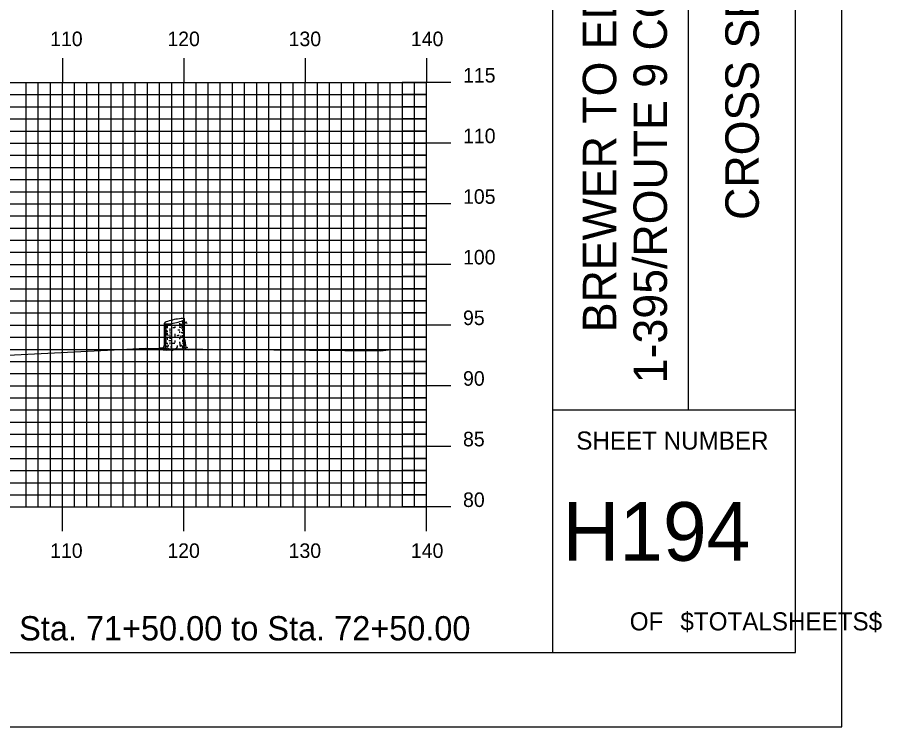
# Model space of a CAD drawing. Extents: x 1760610 to 1760954, y 442591 to 442811.
# Drawn here: x 1760882.5 to 1760953.7, y 442590.5 to 442649 of the extents above; entities that cross this region are included whole.
import ezdxf

# ---------------------------------------------------------------- set-up
doc = ezdxf.new("R2010")
doc.units = 0
for name, color, linetype in [('BORDER', 7, 'Continuous'), ('H_V ANNOTATION', 7, 'Continuous'), ('M_Trees_Conifer_Pay', 7, 'Continuous'), ('MAJOR', 7, 'Continuous'), ('MINOR', 7, 'Continuous'), ('PLOT BOUNDARY', 7, 'Continuous'), ('S_Roadway_Centerline', 7, 'Continuous')]:
    doc.layers.add(name, color=color, linetype=linetype)

msp = doc.modelspace()

# ---------------------------------------------------------------- linework, layer by layer
at = {"layer": 'BORDER'}
for p, q in [((1760926.614, 442596.665), (1760926.614, 442806.665)), ((1760937.796, 442616.671), (1760937.796, 442686.671)), ((1760926.614, 442616.671), (1760946.614, 442616.671))]:
    msp.add_line(p, q, dxfattribs=at)
msp.add_lwpolyline([(1760626.614, 442596.665), (1760946.614, 442596.665), (1760946.614, 442806.665), (1760626.614, 442806.665)], close=True, dxfattribs=at)
at = {"layer": 'M_Trees_Conifer_Pay'}
for p, q in [((1760894.616, 442622.089), (1760894.616, 442623.811)), ((1760894.663, 442623.773), (1760894.663, 442623.302)), ((1760894.722, 442623.762), (1760894.722, 442623.664)), ((1760894.847, 442623.754), (1760894.847, 442623.522)), ((1760895.067, 442623.775), (1760895.067, 442623.607)), ((1760895.863, 442623.817), (1760895.863, 442623.617)), ((1760896.091, 442624.013), (1760896.091, 442623.79)), ((1760896.091, 442623.701), (1760896.091, 442623.654)), ((1760896.209, 442624.074), (1760896.209, 442623.911)), ((1760896.209, 442623.844), (1760896.209, 442623.716)), ((1760896.28, 442622.499), (1760896.28, 442624.146)), ((1760894.663, 442623.238), (1760894.663, 442622.93)), ((1760894.722, 442623.59), (1760894.722, 442623.386)), ((1760894.722, 442623.329), (1760894.722, 442623.129)), ((1760894.722, 442623.082), (1760894.722, 442622.746)), ((1760894.847, 442623.481), (1760894.847, 442623.407)), ((1760894.847, 442623.004), (1760894.847, 442622.865)), ((1760895.067, 442623.37), (1760895.067, 442623.133)), ((1760895.472, 442623.543), (1760895.472, 442623.448)), ((1760895.863, 442623.56), (1760895.863, 442623.471)), ((1760895.863, 442623.123), (1760895.863, 442623.018)), ((1760896.091, 442623.319), (1760896.091, 442623.187)), ((1760896.091, 442623.076), (1760896.091, 442622.966)), ((1760896.148, 442623.518), (1760896.097, 442623.458)), ((1760896.209, 442623.529), (1760896.209, 442623.193)), ((1760896.209, 442623.156), (1760896.209, 442622.993)), ((1760896.209, 442622.946), (1760896.209, 442622.729)), ((1760894.663, 442622.882), (1760894.663, 442622.39)), ((1760894.663, 442622.336), (1760894.663, 442622.089)), ((1760894.722, 442622.693), (1760894.722, 442622.557)), ((1760894.722, 442622.458), (1760894.722, 442622.079)), ((1760894.847, 442622.594), (1760894.847, 442622.452)), ((1760895.067, 442622.888), (1760895.067, 442622.736)), ((1760895.067, 442622.693), (1760895.067, 442622.519)), ((1760895.067, 442622.242), (1760895.067, 442622.089)), ((1760895.472, 442622.93), (1760895.472, 442622.855)), ((1760895.472, 442622.831), (1760895.472, 442622.682)), ((1760895.472, 442622.39), (1760895.472, 442622.237)), ((1760895.863, 442622.651), (1760895.863, 442622.505)), ((1760895.863, 442622.273), (1760895.863, 442622.184)), ((1760896.091, 442622.831), (1760896.091, 442622.689)), ((1760896.091, 442622.462), (1760896.091, 442622.289)), ((1760896.209, 442622.699), (1760896.209, 442622.624)), ((1760896.209, 442622.584), (1760896.209, 442622.411)), ((1760894.847, 442622.19), (1760894.847, 442622.096)), ((1760894.847, 442621.696), (1760895.01, 442621.76)), ((1760895.284, 442621.632), (1760895.158, 442621.696))]:
    msp.add_line(p, q, dxfattribs=at)
for points in [[(1760896.097, 442623.644), (1760896.134, 442623.57), (1760896.181, 442623.627), (1760896.239, 442623.695), (1760896.331, 442623.889), (1760896.396, 442623.936), (1760896.427, 442623.943)], [(1760896.112, 442623.391), (1760896.148, 442623.518), (1760896.212, 442623.634), (1760896.243, 442623.701), (1760896.312, 442623.848)], [(1760896.326, 442623.877), (1760896.402, 442623.885), (1760896.474, 442623.786)], [(1760894.795, 442623.117), (1760894.789, 442623.212), (1760894.833, 442623.189), (1760894.833, 442623.094)], [(1760896.064, 442623.607), (1760896.033, 442623.522), (1760896.029, 442623.455), (1760896.06, 442623.391)], [(1760896.28, 442622.499), (1760896.331, 442622.237), (1760896.348, 442621.964), (1760896.406, 442621.838), (1760896.541, 442621.808), (1760896.311, 442621.77), (1760896.311, 442621.77), (1760896.317, 442621.723), (1760896.564, 442621.628), (1760896.29, 442621.645), (1760895.934, 442621.665), (1760895.613, 442621.655), (1760895.619, 442621.737), (1760895.471, 442621.655), (1760895.284, 442621.632), (1760895.308, 442621.564), (1760895.041, 442621.607), (1760894.82, 442621.581), (1760894.528, 442621.598), (1760894.816, 442621.655), (1760894.847, 442621.696), (1760894.684, 442621.754), (1760894.448, 442621.764), (1760894.207, 442621.764), (1760894.549, 442621.822), (1760894.59, 442621.902), (1760894.616, 442622.089)], [(1760895.934, 442622.718), (1760895.947, 442622.641), (1760895.994, 442622.651), (1760895.982, 442622.818)], [(1760896.206, 442622.357), (1760896.212, 442622.211), (1760896.259, 442622.143), (1760896.27, 442621.943)], [(1760894.664, 442622.042), (1760894.643, 442621.964), (1760894.623, 442621.869)], [(1760894.742, 442622.021), (1760894.748, 442621.906), (1760894.695, 442621.817), (1760894.684, 442621.754)], [(1760894.905, 442622.048), (1760894.905, 442621.916), (1760894.816, 442621.817)], [(1760895.131, 442621.808), (1760895.199, 442621.902), (1760895.226, 442622.042)], [(1760895.619, 442621.737), (1760895.694, 442621.879), (1760895.703, 442621.98)], [(1760895.87, 442622.106), (1760895.881, 442621.98), (1760895.955, 442621.937)], [(1760896.148, 442621.717), (1760896.134, 442621.855), (1760896.06, 442621.984)], [(1760896.107, 442622.211), (1760896.181, 442622.106), (1760896.186, 442621.933), (1760896.311, 442621.77)]]:
    msp.add_lwpolyline(points, dxfattribs=at)
for centre, radius, start, end in [((1760894.643, 442623.811), 0.0264, 169.2194, 180.03145), ((1760894.639, 442623.811), 0.0226, 180.03145, 191.7194), ((1760894.648, 442623.81), 0.0314, 156.51582, 169.2194), ((1760894.639, 442623.811), 0.0226, 191.7194, 203.40735), ((1760894.642, 442623.812), 0.0264, 203.40735, 214.2194), ((1760894.667, 442623.801), 0.0527, 146.7194, 156.51582), ((1760894.647, 442623.815), 0.0314, 214.2194, 226.92298), ((1760894.691, 442623.785), 0.0817, 132.38868, 146.7194), ((1760894.661, 442623.83), 0.0527, 226.92298, 236.7194), ((1760894.677, 442623.855), 0.0817, 236.7194, 251.05013), ((1760894.805, 442623.66), 0.251, 124.2194, 132.38868), ((1760894.732, 442624.014), 0.251, 251.05013, 259.2194), ((1760895.115, 442623.205), 0.802, 108.05939, 124.2194), ((1760894.835, 442624.556), 0.802, 259.2194, 275.37941), ((1760896.472, 442619.043), 5.179, 101.7194, 108.05939), ((1760894.425, 442628.914), 5.179, 275.37941, 281.7194), ((1760895.448, 442627.823), 4.124, 264.6955, 266.73309), ((1760896.472, 442619.043), 5.179, 95.37941, 101.7194), ((1760894.425, 442628.914), 5.179, 281.7194, 288.05939), ((1760895.448, 442627.823), 4.124, 276.23804, 278.1032), ((1760896.062, 442623.401), 0.802, 79.2194, 95.37941), ((1760895.781, 442624.752), 0.802, 288.05939, 304.2194), ((1760895.949, 442624.305), 0.571, 278.1032, 284.36665), ((1760895.949, 442624.46), 0.571, 284.43166, 292.41325), ((1760895.949, 442624.305), 0.571, 297.0237, 300), ((1760896.165, 442623.942), 0.251, 71.05013, 79.2194), ((1760896.091, 442624.296), 0.251, 304.2194, 312.38868), ((1760896.148, 442624.115), 0.172, 300, 311.25059), ((1760896.148, 442623.96), 0.172, 300, 311.25059), ((1760896.22, 442624.102), 0.0817, 56.7194, 71.05013), ((1760896.205, 442624.172), 0.0817, 312.38868, 326.7194), ((1760896.221, 442624.032), 0.0624, 311.25059, 330), ((1760896.221, 442623.878), 0.0624, 311.25059, 330), ((1760896.235, 442624.126), 0.0527, 46.92298, 56.7194), ((1760896.25, 442624.142), 0.0314, 34.2194, 46.92298), ((1760896.229, 442624.156), 0.0527, 326.7194, 336.51582), ((1760896.237, 442624.023), 0.0441, 330, 343.94846), ((1760896.237, 442623.868), 0.0441, 330, 343.94846), ((1760896.254, 442624.145), 0.0264, 23.40735, 34.2194), ((1760896.258, 442624.146), 0.0226, 11.7194, 23.40735), ((1760896.249, 442624.147), 0.0314, 336.51582, 349.2194), ((1760896.247, 442624.02), 0.0334, 343.94846, 354.21506), ((1760896.247, 442623.865), 0.0334, 343.94846, 354.21506), ((1760896.258, 442624.146), 0.0226, 0.03145, 11.7194), ((1760896.254, 442624.146), 0.0264, 349.2194, 0.03145), ((1760894.648, 442623.633), 0.0334, 163.94846, 180), ((1760894.648, 442623.633), 0.0334, 180, 196.05154), ((1760894.648, 442623.186), 0.0334, 163.94846, 180), ((1760894.648, 442623.186), 0.0334, 180, 196.05154), ((1760894.648, 442622.976), 0.0334, 163.94846, 180), ((1760894.648, 442622.976), 0.0334, 180, 196.05154), ((1760894.659, 442623.636), 0.0441, 196.05154, 210), ((1760894.659, 442623.189), 0.0441, 196.05154, 210), ((1760894.659, 442622.979), 0.0441, 196.05154, 210), ((1760894.674, 442623.645), 0.0624, 210, 228.74941), ((1760894.674, 442623.198), 0.0624, 210, 228.74941), ((1760894.674, 442622.988), 0.0624, 210, 228.74941), ((1760894.747, 442623.727), 0.172, 228.74941, 240), ((1760894.747, 442623.28), 0.172, 228.74941, 240), ((1760894.747, 442623.07), 0.172, 228.74941, 240), ((1760894.946, 442624.072), 0.571, 240, 240.33672), ((1760894.946, 442623.626), 0.571, 240, 240.33672), ((1760894.947, 442623.861), 0.571, 240, 247.05866), ((1760894.946, 442624.072), 0.571, 246.85973, 257.98457), ((1760895.447, 442627.143), 4.124, 264.08098, 266.66759), ((1760895.447, 442627.59), 4.124, 268.07512, 270), ((1760895.447, 442627.59), 4.124, 270, 270.35814), ((1760895.448, 442627.379), 4.124, 273.70524, 275.95043), ((1760895.447, 442627.59), 4.124, 275.78493, 277.05584), ((1760895.447, 442627.143), 4.124, 277.61247, 278.1032), ((1760895.948, 442623.626), 0.571, 278.1032, 286.92962), ((1760895.949, 442623.861), 0.571, 284.44928, 297.04285), ((1760895.948, 442623.626), 0.571, 297.18959, 300), ((1760896.147, 442623.28), 0.172, 300, 311.25059), ((1760896.147, 442623.07), 0.172, 300, 311.25059), ((1760896.219, 442623.198), 0.0624, 311.25059, 330), ((1760896.219, 442622.988), 0.0624, 311.25059, 330), ((1760896.235, 442623.189), 0.0441, 330, 343.94846), ((1760896.235, 442622.979), 0.0441, 330, 343.94846), ((1760896.246, 442623.186), 0.0334, 343.94846, 354.21506), ((1760896.246, 442622.976), 0.0334, 343.94846, 354.21506), ((1760896.247, 442623.421), 0.0334, 343.94846, 354.21506), ((1760894.648, 442622.739), 0.0334, 163.94846, 180), ((1760894.648, 442622.739), 0.0334, 180, 196.05154), ((1760894.648, 442622.541), 0.0334, 163.94846, 180), ((1760894.648, 442622.346), 0.0334, 163.94846, 180), ((1760894.648, 442622.346), 0.0334, 180, 196.05154), ((1760894.659, 442622.742), 0.0441, 196.05154, 210), ((1760894.659, 442622.349), 0.0441, 196.05154, 210), ((1760894.674, 442622.751), 0.0624, 210, 228.74941), ((1760894.674, 442622.358), 0.0624, 210, 228.74941), ((1760894.747, 442622.834), 0.172, 228.74941, 240), ((1760894.747, 442622.44), 0.172, 228.74941, 240), ((1760894.946, 442623.416), 0.571, 240, 246.85973), ((1760894.946, 442623.179), 0.571, 240, 246.85973), ((1760894.935, 442622.987), 0.571, 241.23686, 248.02677), ((1760894.946, 442622.785), 0.571, 240, 246.85973), ((1760894.946, 442623.416), 0.571, 259.27072, 261.8968), ((1760895.447, 442626.933), 4.124, 261.8968, 263.14738), ((1760895.447, 442626.499), 4.124, 263.49906, 265.83975), ((1760895.447, 442626.696), 4.124, 264.71603, 266.31934), ((1760895.447, 442626.933), 4.124, 270, 270.35814), ((1760895.447, 442626.933), 4.124, 273.14934, 275.45691), ((1760895.948, 442623.179), 0.571, 285.39827, 297.18959), ((1760895.948, 442622.785), 0.571, 288.50673, 297.27208), ((1760895.948, 442622.981), 0.571, 289.29072, 300), ((1760895.948, 442623.416), 0.571, 297.18959, 300), ((1760896.147, 442622.636), 0.172, 300, 311.25059), ((1760896.219, 442622.553), 0.0624, 311.25059, 330), ((1760896.235, 442622.544), 0.0441, 330, 343.94846), ((1760896.246, 442622.541), 0.0334, 343.94846, 354.21506), ((1760894.648, 442622.125), 0.0334, 163.94846, 180), ((1760894.648, 442622.125), 0.0334, 180, 196.05154), ((1760894.659, 442622.128), 0.0441, 196.05154, 210), ((1760894.674, 442622.137), 0.0624, 210, 228.74941), ((1760894.747, 442622.22), 0.172, 228.74941, 240), ((1760894.946, 442622.565), 0.571, 240, 244.53138), ((1760895.447, 442626.083), 4.124, 262.44379, 263.51202), ((1760895.447, 442626.303), 4.124, 267.81166, 270), ((1760895.447, 442626.303), 4.124, 270, 270.13279), ((1760895.447, 442626.303), 4.124, 275.78493, 276.78961), ((1760895.447, 442626.083), 4.124, 277.36842, 278.1032), ((1760895.948, 442622.565), 0.571, 278.1032, 281.63703), ((1760896.147, 442622.22), 0.172, 300, 311.25059), ((1760896.219, 442622.137), 0.0624, 311.25059, 330), ((1760896.235, 442622.128), 0.0441, 330, 343.94846), ((1760896.246, 442622.125), 0.0334, 343.94846, 354.21506)]:
    msp.add_arc(centre, radius, start, end, dxfattribs=at)
at = {"layer": 'MAJOR'}
for p, q in [((1760886.214, 442645.669), (1760886.214, 442643.665)), ((1760896.214, 442645.669), (1760896.214, 442643.665)), ((1760906.214, 442645.669), (1760906.214, 442643.665)), ((1760916.214, 442645.669), (1760916.214, 442643.665)), ((1760636.214, 442643.665), (1760916.214, 442643.665)), ((1760636.214, 442643.665), (1760916.214, 442643.665)), ((1760886.214, 442608.665), (1760886.214, 442643.665)), ((1760896.214, 442608.665), (1760896.214, 442643.665)), ((1760906.214, 442608.665), (1760906.214, 442643.665)), ((1760918.218, 442643.665), (1760914.21, 442643.665)), ((1760916.214, 442608.665), (1760916.214, 442643.665)), ((1760916.214, 442608.665), (1760916.214, 442643.665)), ((1760636.214, 442638.665), (1760916.214, 442638.665)), ((1760918.218, 442638.665), (1760914.21, 442638.665)), ((1760636.214, 442633.665), (1760916.214, 442633.665)), ((1760918.218, 442633.665), (1760914.21, 442633.665)), ((1760636.214, 442628.665), (1760916.214, 442628.665)), ((1760918.218, 442628.665), (1760914.21, 442628.665)), ((1760636.214, 442623.665), (1760916.214, 442623.665)), ((1760918.218, 442623.665), (1760914.21, 442623.665)), ((1760636.214, 442618.665), (1760916.214, 442618.665)), ((1760918.218, 442618.665), (1760914.21, 442618.665)), ((1760636.214, 442613.665), (1760916.214, 442613.665)), ((1760918.218, 442613.665), (1760914.21, 442613.665)), ((1760636.214, 442608.665), (1760916.214, 442608.665)), ((1760636.214, 442608.665), (1760916.214, 442608.665)), ((1760886.214, 442606.661), (1760886.214, 442608.665)), ((1760896.214, 442606.661), (1760896.214, 442608.665)), ((1760906.214, 442606.661), (1760906.214, 442608.665)), ((1760918.218, 442608.665), (1760914.21, 442608.665)), ((1760916.214, 442606.661), (1760916.214, 442608.665))]:
    msp.add_line(p, q, dxfattribs=at)
at = {"layer": 'MINOR'}
for p, q in [((1760883.214, 442608.665), (1760883.214, 442643.665)), ((1760884.214, 442608.665), (1760884.214, 442643.665)), ((1760885.214, 442608.665), (1760885.214, 442643.665)), ((1760887.214, 442608.665), (1760887.214, 442643.665)), ((1760888.214, 442608.665), (1760888.214, 442643.665)), ((1760889.214, 442608.665), (1760889.214, 442643.665)), ((1760890.214, 442608.665), (1760890.214, 442643.665)), ((1760891.214, 442608.665), (1760891.214, 442643.665)), ((1760892.214, 442608.665), (1760892.214, 442643.665)), ((1760893.214, 442608.665), (1760893.214, 442643.665)), ((1760894.214, 442608.665), (1760894.214, 442643.665)), ((1760895.214, 442608.665), (1760895.214, 442643.665)), ((1760897.214, 442608.665), (1760897.214, 442643.665)), ((1760898.214, 442608.665), (1760898.214, 442643.665)), ((1760899.214, 442608.665), (1760899.214, 442643.665)), ((1760900.214, 442608.665), (1760900.214, 442643.665)), ((1760901.214, 442608.665), (1760901.214, 442643.665)), ((1760902.214, 442608.665), (1760902.214, 442643.665)), ((1760903.214, 442608.665), (1760903.214, 442643.665)), ((1760904.214, 442608.665), (1760904.214, 442643.665)), ((1760905.214, 442608.665), (1760905.214, 442643.665)), ((1760907.214, 442608.665), (1760907.214, 442643.665)), ((1760908.214, 442608.665), (1760908.214, 442643.665)), ((1760909.214, 442608.665), (1760909.214, 442643.665)), ((1760910.214, 442608.665), (1760910.214, 442643.665)), ((1760911.214, 442608.665), (1760911.214, 442643.665)), ((1760912.214, 442608.665), (1760912.214, 442643.665)), ((1760913.214, 442608.665), (1760913.214, 442643.665)), ((1760914.214, 442608.665), (1760914.214, 442643.665)), ((1760915.214, 442608.665), (1760915.214, 442643.665)), ((1760636.214, 442642.665), (1760916.214, 442642.665)), ((1760916.214, 442642.665), (1760914.21, 442642.665)), ((1760636.214, 442641.665), (1760916.214, 442641.665)), ((1760916.214, 442641.665), (1760914.21, 442641.665)), ((1760636.214, 442640.665), (1760916.214, 442640.665)), ((1760916.214, 442640.665), (1760914.21, 442640.665)), ((1760636.214, 442639.665), (1760916.214, 442639.665)), ((1760916.214, 442639.665), (1760914.21, 442639.665)), ((1760636.214, 442637.665), (1760916.214, 442637.665)), ((1760916.214, 442637.665), (1760914.21, 442637.665)), ((1760636.214, 442636.665), (1760916.214, 442636.665)), ((1760916.214, 442636.665), (1760914.21, 442636.665)), ((1760636.214, 442635.665), (1760916.214, 442635.665)), ((1760916.214, 442635.665), (1760914.21, 442635.665)), ((1760636.214, 442634.665), (1760916.214, 442634.665)), ((1760916.214, 442634.665), (1760914.21, 442634.665)), ((1760636.214, 442632.665), (1760916.214, 442632.665)), ((1760916.214, 442632.665), (1760914.21, 442632.665)), ((1760636.214, 442631.665), (1760916.214, 442631.665)), ((1760916.214, 442631.665), (1760914.21, 442631.665)), ((1760636.214, 442630.665), (1760916.214, 442630.665)), ((1760916.214, 442630.665), (1760914.21, 442630.665)), ((1760636.214, 442629.665), (1760916.214, 442629.665)), ((1760916.214, 442629.665), (1760914.21, 442629.665)), ((1760636.214, 442627.665), (1760916.214, 442627.665)), ((1760916.214, 442627.665), (1760914.21, 442627.665)), ((1760636.214, 442626.665), (1760916.214, 442626.665)), ((1760916.214, 442626.665), (1760914.21, 442626.665)), ((1760636.214, 442625.665), (1760916.214, 442625.665)), ((1760916.214, 442625.665), (1760914.21, 442625.665)), ((1760636.214, 442624.665), (1760916.214, 442624.665)), ((1760916.214, 442624.665), (1760914.21, 442624.665)), ((1760636.214, 442622.665), (1760916.214, 442622.665)), ((1760916.214, 442622.665), (1760914.21, 442622.665)), ((1760636.214, 442621.665), (1760916.214, 442621.665)), ((1760916.214, 442621.665), (1760914.21, 442621.665)), ((1760636.214, 442620.665), (1760916.214, 442620.665)), ((1760916.214, 442620.665), (1760914.21, 442620.665)), ((1760636.214, 442619.665), (1760916.214, 442619.665)), ((1760916.214, 442619.665), (1760914.21, 442619.665)), ((1760636.214, 442617.665), (1760916.214, 442617.665)), ((1760916.214, 442617.665), (1760914.21, 442617.665)), ((1760636.214, 442616.665), (1760916.214, 442616.665)), ((1760916.214, 442616.665), (1760914.21, 442616.665)), ((1760636.214, 442615.665), (1760916.214, 442615.665)), ((1760916.214, 442615.665), (1760914.21, 442615.665)), ((1760636.214, 442614.665), (1760916.214, 442614.665)), ((1760916.214, 442614.665), (1760914.21, 442614.665)), ((1760636.214, 442612.665), (1760916.214, 442612.665)), ((1760916.214, 442612.665), (1760914.21, 442612.665)), ((1760636.214, 442611.665), (1760916.214, 442611.665)), ((1760916.214, 442611.665), (1760914.21, 442611.665)), ((1760636.214, 442610.665), (1760916.214, 442610.665)), ((1760916.214, 442610.665), (1760914.21, 442610.665)), ((1760636.214, 442609.665), (1760916.214, 442609.665)), ((1760916.214, 442609.665), (1760914.21, 442609.665))]:
    msp.add_line(p, q, dxfattribs=at)
at = {"layer": 'PLOT BOUNDARY'}
msp.add_lwpolyline([(1760610.427, 442590.547), (1760950.427, 442590.547), (1760950.427, 442810.547), (1760610.427, 442810.547)], close=True, dxfattribs=at)
at = {"layer": 'S_Roadway_Centerline'}
msp.add_lwpolyline([(1760826.497, 442620.077), (1760845.028, 442620.401), (1760850.348, 442620.466), (1760859.484, 442620.651), (1760868.115, 442620.759), (1760871.292, 442620.879), (1760874.582, 442620.84), (1760890.481, 442621.63), (1760893.053, 442621.767), (1760897.765, 442621.691), (1760912.424, 442621.532), (1760913.081, 442621.632), (1760916.214, 442621.646)], dxfattribs=at)

# ---------------------------------------------------------------- texts
at = {"layer": 'BORDER'}
for s, p in [('1-395/ROUTE 9 CONNECTOR', (1760936.016, 442618.865)), ('BREWER TO EDDINGTON', (1760931.837, 442623.074)), ('CROSS SECTIONS', (1760943.583, 442632.339))]:
    msp.add_text(s, height=2.75575, rotation=90, dxfattribs=at).set_placement(p)
for s, height, p in [('SHEET NUMBER', 1.49054, (1760928.545, 442613.398)), ('H194', 4.8388, (1760927.416, 442604.23)), ('OF', 1.4905, (1760932.948, 442598.491)), ('$TOTALSHEETS$', 1.49054, (1760937.127, 442598.491))]:
    msp.add_text(s, height=height, dxfattribs=at).set_placement(p)
at = {"layer": 'H_V ANNOTATION'}
for s, height, p in [('110', 1.2, (1760885.197, 442646.665)), ('120', 1.2, (1760894.854, 442646.665)), ('130', 1.2, (1760904.844, 442646.665)), ('140', 1.2, (1760914.919, 442646.665)), ('115', 1.2, (1760919.214, 442643.665)), ('110', 1.2, (1760919.214, 442638.665)), ('105', 1.2, (1760919.214, 442633.665)), ('100', 1.2, (1760919.214, 442628.665)), ('95', 1.2, (1760919.214, 442623.665)), ('90', 1.2, (1760919.214, 442618.665)), ('85', 1.2, (1760919.214, 442613.665)), ('80', 1.2, (1760919.214, 442608.665)), ('110', 1.2, (1760885.197, 442604.465)), ('120', 1.2, (1760894.854, 442604.465)), ('130', 1.2, (1760904.844, 442604.465)), ('140', 1.2, (1760914.919, 442604.465)), ('Sta. 71+50.00 to Sta. 72+50.00', 2.0004, (1760882.644, 442597.665))]:
    msp.add_text(s, height=height, dxfattribs=at).set_placement(p)

doc.saveas('drawing.dxf')
